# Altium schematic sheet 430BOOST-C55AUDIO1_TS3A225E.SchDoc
size A4; PageSetup: Record=PageOptions|CenterHorizontal=True|CenterVertical=True|PrintScale=0.97|XCorrection=1.00|YCorrection=1.00|PrintKind=0|BorderSize=5000000|LeftOffset=0|BottomOffset=0|Orientation=2|PaperLength=1000|PaperWidth=1000|Scale=100|PaperSource=15|PrintQuality=1200|MediaType=1|DitherType=10|PaperKind=A4|PrintScaleMode=1
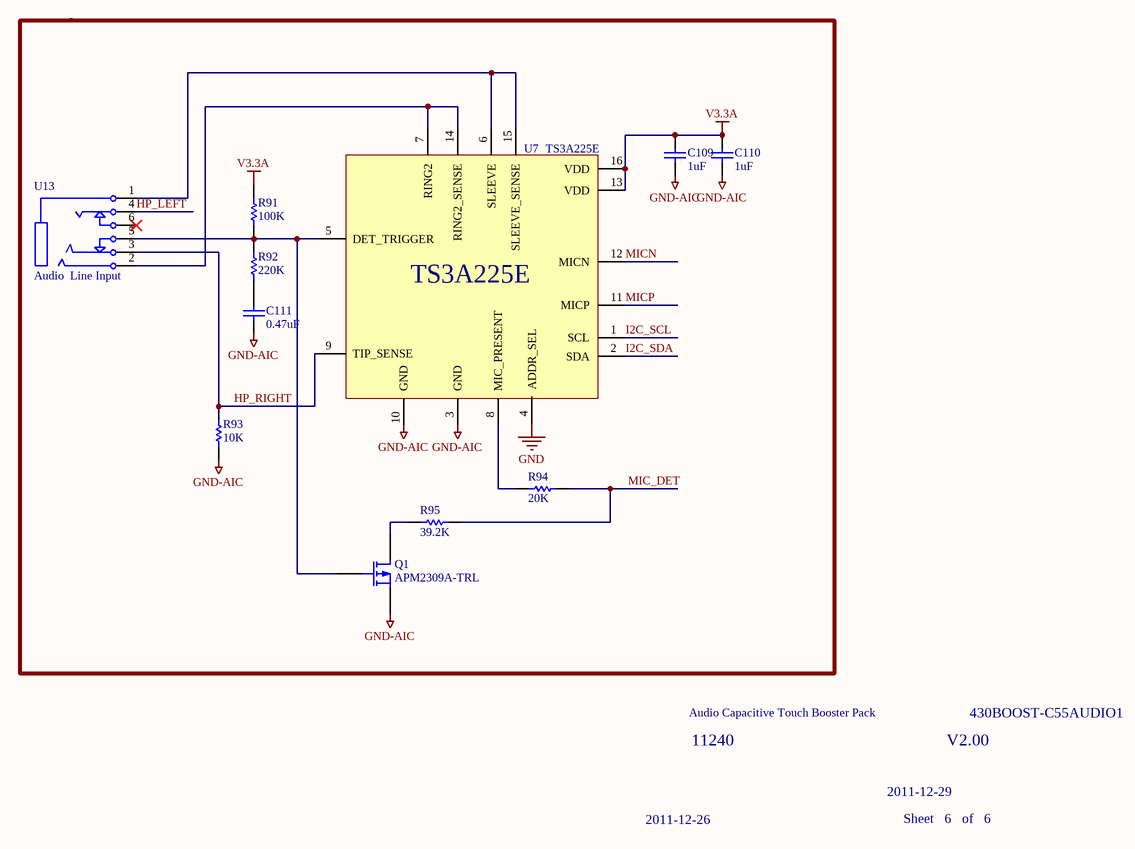
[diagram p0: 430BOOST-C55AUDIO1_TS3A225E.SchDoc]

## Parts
C109  1uF  [0603-C]
C110  1uF  [0603-C]
C111  0.47uF  [0402-C]
Q1  APM2309A-TRL  [SOT-23-3P]
R91  100K  [0402-R]
R92  220K  [0402-R]
R93  10K  [0402-R]
R94  20K  [0402-R]
R95  39.2K  [0402-R]
U7  TS3A225E  [QFN-16P-0.5MM]
U13  Audio  Line Input  [KJ-355-X1]

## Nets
GND: U7.4(ADDR_SEL)
GND-AIC: C109.1 C110.1 C111.1 Q1.2(S) R93.1 U7.3(GND) U7.10(GND)
V3.3A: C109.2 C110.2 R91.2 U7.13(VDD) U7.16(VDD)
HP_LEFT: U13.4
HP_RIGHT: R93.2 U7.9(TIP_SENSE) U13.3
I2C_SCL: U7.1(SCL)
I2C_SDA: U7.2(SDA)
MIC_DET: R94.2 R95.2
MICN: U7.12(MICN)
MICP: U7.11(MICP)
NetC111_2: C111.2 R92.1
NetQ1_1: Q1.1(G) R91.1 R92.2 U7.5(DET_TRIGGER) U13.5
NetQ1_3: Q1.3(D) R95.1
NetR94_1: R94.1 U7.8(MIC_PRESENT)
NetU7_6: U7.6(SLEEVE) U7.15(SLEEVE_SENSE) U13.1
NetU7_7: U7.7(RING2) U7.14(RING2_SENSE) U13.2

Not connected (* = marked no-connect by the designer): U13 6*

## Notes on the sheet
- Audio Capacitive Touch Booster Pack
- 430BOOST-C55AUDIO1
- 11240
- V2.00
- 2011-12-26
- 2011-12-29
- Sheet   6   of   6

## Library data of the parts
C109-C111 = Cap: Capacitor; Value: 100pF
Q1 = MOSFET-P: P-Channel MOSFET
R91-R95 = Res1: Resistor; Value: 1K
U13 = Audio_2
